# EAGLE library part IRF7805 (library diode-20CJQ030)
Internation Rectifier's IRF7805 HEXFET® Chip-Set for DC-DC Converters Description: This new device employs advanced HEXFET Power MOSFET technology to achieve an unprecedented balance of on-resistance and gate charge. The reduced conduction and switching losses make this device ideal for high efficiency DC-DC Converters that power the latest generation of mobile microprocessors. The IRF7805 offers maximum efficiency for mobile CPU core DC-DC converters. N Channel Application Specific MOSFETs Ideal for Mobile DC-DC Converters Low Conduction Losses Low Switching Losses VDS = 30V RDS(on) = 11mOhm Qg = 31nC Please send any comments to: messi@users.sourceforge.net
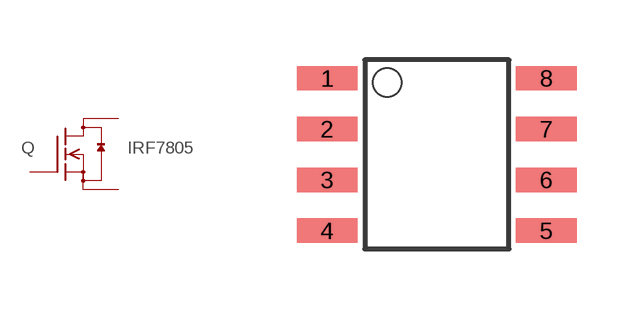
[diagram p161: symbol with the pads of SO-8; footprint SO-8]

Designator prefix Q

## IRF7805  [SO-8]
1  S  pas
2  S  pas
3  S  pas
4  G  pas
5  D  pas
6  D  pas
7  D  pas
8  D  pas

## Footprint SO-8 (pad centres in mm)
small outline
smd 1.524 x 0.61: 1 -2.743,1.27; 2 -2.743,0; 3 -2.743,-1.27; 4 -2.743,-2.54; 5 2.743,-2.54; 6 2.743,-1.27; 7 2.743,0; 8 2.743,1.27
